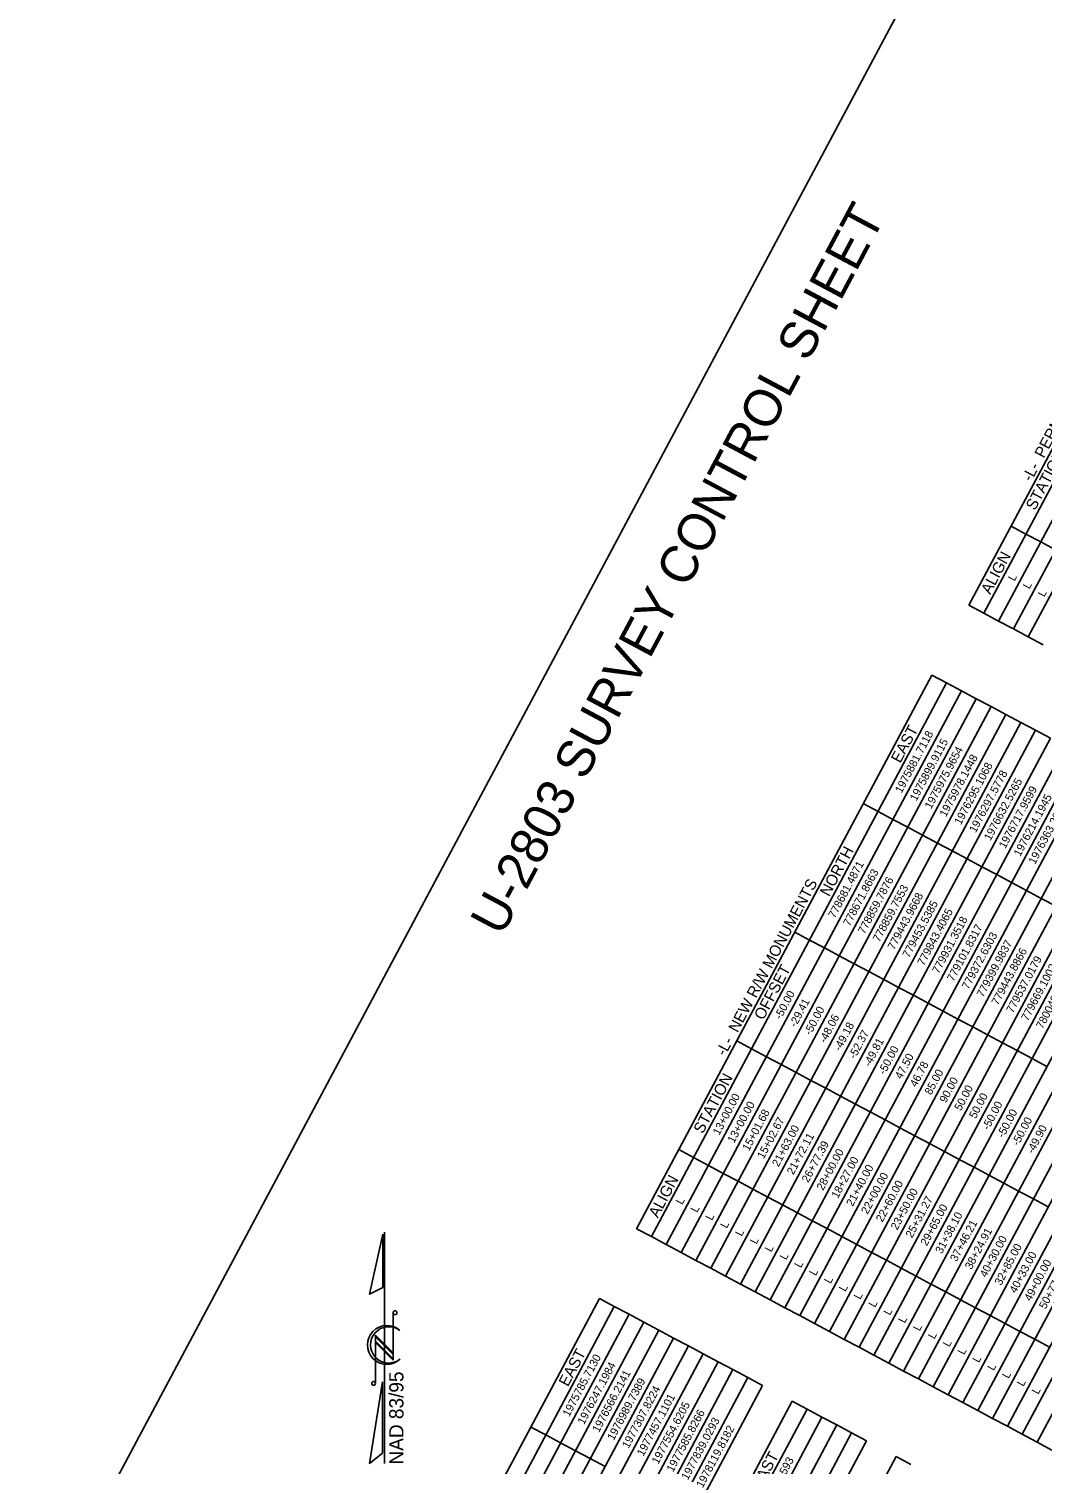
# Model space of a CAD drawing. Extents: x 1979034 to 1987549, y 771535 to 781988.
# Drawn here: x 1979034 to 1981883, y 775446 to 779481 of the extents above; entities that cross this region are included whole.
import ezdxf

# ---------------------------------------------------------------- set-up
doc = ezdxf.new("R2010")
doc.units = 0
for name, color, linetype in [('CTL Sheet Border CELL', 7, 'Continuous'), ('CTL Sheet Notes CELL', 7, 'Continuous'), ('CTL Sheet Table Cell', 7, 'Continuous'), ('CTL Sheet Text', 7, 'Continuous'), ('Old_Level_1', 7, 'Continuous'), ('Old_Level_11', 7, 'Continuous'), ('Sheet Data Field CELL', 7, 'Continuous')]:
    doc.layers.add(name, color=color, linetype=linetype)

msp = doc.modelspace()

# ---------------------------------------------------------------- linework, layer by layer
at = {"layer": 'CTL Sheet Border CELL'}
msp.add_lwpolyline([(1982714.7, 781848.1), (1979034.2, 774941.4), (1983868.8, 772365.1), (1987549.3, 779271.7)], close=True, dxfattribs=at)
at = {"layer": 'CTL Sheet Table Cell'}
for p, q in [((1981677, 777860.7), (1982506.6, 779417.5)), ((1981718.7, 777838.5), (1982548.3, 779395.2)), ((1981760.4, 777816.3), (1982590, 779373)), ((1981802.1, 777794), (1982631.7, 779350.8)), ((1981843.8, 777771.8), (1982673.4, 779328.6)), ((1981795.5, 778083.1), (1981837.2, 778060.9)), ((1981837.2, 778060.9), (1981878.9, 778038.7)), ((1981878.9, 778038.7), (1981920.6, 778016.4)), ((1981677, 777860.7), (1981718.7, 777838.5)), ((1981718.7, 777838.5), (1981760.4, 777816.3)), ((1981760.4, 777816.3), (1981802.1, 777794)), ((1981802.1, 777794), (1981843.8, 777771.8)), ((1981843.8, 777771.8), (1981885.5, 777749.6)), ((1980742.9, 776107.8), (1981572.5, 777664.5)), ((1981572.5, 777664.5), (1981614.2, 777642.3)), ((1980784.6, 776085.6), (1981614.2, 777642.3)), ((1980826.3, 776063.3), (1981655.9, 777620.1)), ((1981614.2, 777642.3), (1981655.9, 777620.1)), ((1981655.9, 777620.1), (1981697.6, 777597.9)), ((1980868, 776041.1), (1981697.6, 777597.9)), ((1980909.7, 776018.9), (1981739.3, 777575.7)), ((1981697.6, 777597.9), (1981739.3, 777575.7)), ((1981739.3, 777575.7), (1981781, 777553.4)), ((1980951.4, 775996.7), (1981781, 777553.4)), ((1980993.1, 775974.5), (1981822.7, 777531.2)), ((1981781, 777553.4), (1981822.7, 777531.2)), ((1981822.7, 777531.2), (1981864.4, 777509)), ((1981034.8, 775952.2), (1981864.4, 777509)), ((1981076.5, 775930), (1981906.1, 777486.8)), ((1981864.4, 777509), (1981906.1, 777486.8)), ((1981118.2, 775907.8), (1981947.8, 777464.6)), ((1981159.9, 775885.6), (1981989.5, 777442.3)), ((1981201.6, 775863.4), (1982031.2, 777420.1)), ((1981243.3, 775841.1), (1982072.9, 777397.9)), ((1981285, 775818.9), (1982114.6, 777375.7)), ((1981326.7, 775796.7), (1982156.3, 777353.5)), ((1981368.4, 775774.5), (1982198, 777331.2)), ((1981379.9, 777303.2), (1981421.6, 777280.9)), ((1981410.1, 775752.3), (1982239.7, 777309)), ((1981421.6, 777280.9), (1981463.3, 777258.7)), ((1981451.8, 775730), (1982281.4, 777286.8)), ((1981463.3, 777258.7), (1981505, 777236.5)), ((1981493.5, 775707.8), (1982323.1, 777264.6)), ((1981535.2, 775685.6), (1982364.8, 777242.3)), ((1981505, 777236.5), (1981546.7, 777214.3)), ((1981546.7, 777214.3), (1981588.4, 777192.1)), ((1981576.9, 775663.4), (1982406.5, 777220.1)), ((1981588.4, 777192.1), (1981630.1, 777169.8)), ((1981618.6, 775641.1), (1982448.2, 777197.9)), ((1981630.1, 777169.8), (1981671.8, 777147.6)), ((1981660.3, 775618.9), (1982489.9, 777175.7)), ((1981671.8, 777147.6), (1981713.5, 777125.4)), ((1981702, 775596.7), (1982531.6, 777153.5)), ((1981713.5, 777125.4), (1981755.2, 777103.2)), ((1981743.7, 775574.5), (1982573.3, 777131.2)), ((1981755.2, 777103.2), (1981796.9, 777080.9)), ((1981785.4, 775552.3), (1982615, 777109)), ((1981796.9, 777080.9), (1981838.6, 777058.7)), ((1981827.1, 775530), (1982656.7, 777086.8)), ((1981838.6, 777058.7), (1981880.3, 777036.5)), ((1981868.8, 775507.8), (1982698.4, 777064.6)), ((1981880.3, 777036.5), (1981922, 777014.3)), ((1981187.3, 776941.8), (1981229, 776919.5)), ((1981229, 776919.5), (1981270.7, 776897.3)), ((1981270.7, 776897.3), (1981312.4, 776875.1)), ((1981312.4, 776875.1), (1981354.1, 776852.9)), ((1981354.1, 776852.9), (1981395.8, 776830.7)), ((1981395.8, 776830.7), (1981437.5, 776808.4)), ((1981437.5, 776808.4), (1981479.2, 776786.2)), ((1981479.2, 776786.2), (1981520.9, 776764)), ((1981520.9, 776764), (1981562.6, 776741.8)), ((1981562.6, 776741.8), (1981604.3, 776719.6)), ((1981604.3, 776719.6), (1981646, 776697.3)), ((1981646, 776697.3), (1981687.7, 776675.1)), ((1981024.4, 776636), (1981066.1, 776613.8)), ((1981687.7, 776675.1), (1981729.4, 776652.9)), ((1981729.4, 776652.9), (1981771.1, 776630.7)), ((1981066.1, 776613.8), (1981107.8, 776591.5)), ((1981771.1, 776630.7), (1981812.8, 776608.5)), ((1981812.8, 776608.5), (1981854.5, 776586.2)), ((1981107.8, 776591.5), (1981149.5, 776569.3)), ((1981149.5, 776569.3), (1981191.2, 776547.1)), ((1981854.5, 776586.2), (1981896.2, 776564)), ((1981191.2, 776547.1), (1981232.9, 776524.9)), ((1981232.9, 776524.9), (1981274.6, 776502.6)), ((1981274.6, 776502.6), (1981316.3, 776480.4)), ((1981316.3, 776480.4), (1981358, 776458.2)), ((1981358, 776458.2), (1981399.7, 776436)), ((1981399.7, 776436), (1981441.4, 776413.8)), ((1981441.4, 776413.8), (1981483.1, 776391.5)), ((1981483.1, 776391.5), (1981524.8, 776369.3)), ((1981524.8, 776369.3), (1981566.5, 776347.1)), ((1980861.4, 776330.2), (1980903.1, 776308)), ((1981566.5, 776347.1), (1981608.2, 776324.9)), ((1981608.2, 776324.9), (1981649.9, 776302.7)), ((1980903.1, 776308), (1980944.8, 776285.7)), ((1980944.8, 776285.7), (1980986.5, 776263.5)), ((1981649.9, 776302.7), (1981691.6, 776280.4)), ((1981691.6, 776280.4), (1981733.3, 776258.2)), ((1980986.5, 776263.5), (1981028.2, 776241.3)), ((1981028.2, 776241.3), (1981069.9, 776219.1)), ((1981733.3, 776258.2), (1981775, 776236)), ((1981775, 776236), (1981816.7, 776213.8)), ((1981069.9, 776219.1), (1981111.6, 776196.9)), ((1981111.6, 776196.9), (1981153.3, 776174.6)), ((1981816.7, 776213.8), (1981858.4, 776191.6)), ((1981858.4, 776191.6), (1981900.1, 776169.3)), ((1981153.3, 776174.6), (1981195, 776152.4)), ((1981195, 776152.4), (1981236.7, 776130.2)), ((1981236.7, 776130.2), (1981278.4, 776108)), ((1980742.9, 776107.8), (1980784.6, 776085.6)), ((1980784.6, 776085.6), (1980826.3, 776063.3)), ((1981278.4, 776108), (1981320.1, 776085.8)), ((1981320.1, 776085.8), (1981361.8, 776063.5)), ((1980826.3, 776063.3), (1980868, 776041.1)), ((1980868, 776041.1), (1980909.7, 776018.9)), ((1981361.8, 776063.5), (1981403.5, 776041.3)), ((1981403.5, 776041.3), (1981445.2, 776019.1)), ((1980909.7, 776018.9), (1980951.4, 775996.7)), ((1980951.4, 775996.7), (1980993.1, 775974.5)), ((1981445.2, 776019.1), (1981486.9, 775996.9)), ((1981486.9, 775996.9), (1981528.6, 775974.6)), ((1980993.1, 775974.5), (1981034.8, 775952.2)), ((1981034.8, 775952.2), (1981076.5, 775930)), ((1981528.6, 775974.6), (1981570.3, 775952.4)), ((1981570.3, 775952.4), (1981612, 775930.2)), ((1980016.2, 774744.1), (1980638.4, 775911.6)), ((1980638.4, 775911.6), (1980680.1, 775889.4)), ((1981076.5, 775930), (1981118.2, 775907.8)), ((1981612, 775930.2), (1981653.7, 775908)), ((1980057.9, 774721.8), (1980680.1, 775889.4)), ((1980680.1, 775889.4), (1980721.8, 775867.2)), ((1981118.2, 775907.8), (1981159.9, 775885.6)), ((1981159.9, 775885.6), (1981201.6, 775863.4)), ((1981653.7, 775908), (1981695.4, 775885.8)), ((1981695.4, 775885.8), (1981737.1, 775863.5)), ((1980099.6, 774699.6), (1980721.8, 775867.2)), ((1980141.3, 774677.4), (1980763.5, 775845)), ((1980721.8, 775867.2), (1980763.5, 775845)), ((1980763.5, 775845), (1980805.2, 775822.8)), ((1981201.6, 775863.4), (1981243.3, 775841.1)), ((1981243.3, 775841.1), (1981285, 775818.9)), ((1981737.1, 775863.5), (1981778.8, 775841.3)), ((1981778.8, 775841.3), (1981820.5, 775819.1)), ((1980183, 774655.2), (1980805.2, 775822.8)), ((1980224.7, 774633), (1980846.9, 775800.5)), ((1980805.2, 775822.8), (1980846.9, 775800.5)), ((1980846.9, 775800.5), (1980888.6, 775778.3)), ((1981285, 775818.9), (1981326.7, 775796.7)), ((1981326.7, 775796.7), (1981368.4, 775774.5)), ((1981820.5, 775819.1), (1981862.2, 775796.9)), ((1981862.2, 775796.9), (1981903.9, 775774.7)), ((1980266.4, 774610.7), (1980888.6, 775778.3)), ((1980308.1, 774588.5), (1980930.3, 775756.1)), ((1980888.6, 775778.3), (1980930.3, 775756.1)), ((1980930.3, 775756.1), (1980972, 775733.9)), ((1981368.4, 775774.5), (1981410.1, 775752.3)), ((1981410.1, 775752.3), (1981451.8, 775730)), ((1980349.8, 774566.3), (1980972, 775733.9)), ((1980391.5, 774544.1), (1981013.7, 775711.6)), ((1980972, 775733.9), (1981013.7, 775711.6)), ((1981013.7, 775711.6), (1981055.4, 775689.4)), ((1981451.8, 775730), (1981493.5, 775707.8)), ((1981493.5, 775707.8), (1981535.2, 775685.6)), ((1980433.2, 774521.9), (1981055.4, 775689.4)), ((1980474.9, 774499.6), (1981097.1, 775667.2)), ((1981055.4, 775689.4), (1981097.1, 775667.2)), ((1981535.2, 775685.6), (1981576.9, 775663.4)), ((1981576.9, 775663.4), (1981618.6, 775641.1)), ((1981618.6, 775641.1), (1981660.3, 775618.9)), ((1980558.3, 774455.2), (1981180.5, 775622.8)), ((1980600, 774433), (1981222.2, 775600.5)), ((1981180.5, 775622.8), (1981222.2, 775600.5)), ((1981222.2, 775600.5), (1981263.9, 775578.3)), ((1981660.3, 775618.9), (1981702, 775596.7)), ((1981702, 775596.7), (1981743.7, 775574.5)), ((1980445.8, 775550.2), (1980487.5, 775528)), ((1980641.7, 774410.8), (1981263.9, 775578.3)), ((1980683.4, 774388.5), (1981305.6, 775556.1)), ((1981263.9, 775578.3), (1981305.6, 775556.1)), ((1981305.6, 775556.1), (1981347.3, 775533.9)), ((1981743.7, 775574.5), (1981785.4, 775552.3)), ((1981785.4, 775552.3), (1981827.1, 775530)), ((1980487.5, 775528), (1980529.2, 775505.8)), ((1980529.2, 775505.8), (1980570.9, 775483.6)), ((1980725.1, 774366.3), (1981347.3, 775533.9)), ((1980766.8, 774344.1), (1981389, 775511.7)), ((1981347.3, 775533.9), (1981389, 775511.7)), ((1981827.1, 775530), (1981868.8, 775507.8)), ((1981868.8, 775507.8), (1981910.5, 775485.6)), ((1980570.9, 775483.6), (1980612.6, 775461.4)), ((1980850.2, 774299.6), (1981472.4, 775467.2)), ((1981472.4, 775467.2), (1981514.1, 775445)), ((1980612.6, 775461.4), (1980654.3, 775439.1))]:
    msp.add_line(p, q, dxfattribs=at)
at = {"layer": 'Old_Level_1'}
for p, q in [((1980034, 775448), (1980034, 776098)), ((1980058.5, 775871.8), (1980058.5, 775738.4)), ((1980058.5, 775759.2), (1980008.8, 775808.9)), ((1980008.8, 775808.9), (1980008.8, 775673.3)), ((1980058.5, 775754.3), (1980008.8, 775804)), ((1980008.8, 775804), (1980008.8, 775791.8)), ((1980058.5, 775742.1), (1980008.8, 775791.8)), ((1980008.8, 775791.8), (1980058.5, 775742.1)), ((1980058.5, 775738.4), (1980008.8, 775788.1)), ((1980076.9, 775822.1), (1980077.6, 775821.6)), ((1980058.5, 775742.1), (1980058.5, 775754.3))]:
    msp.add_line(p, q, dxfattribs=at)
for points in [[(1980029.5, 776092.3), (1979992.4, 775923.5), (1980029.5, 775942.3)], [(1980028.7, 775677), (1979991.9, 775448), (1980028.7, 775477)]]:
    msp.add_lwpolyline(points, close=True, dxfattribs=at)
for centre in [(1980063.8, 775871.7), (1980003.5, 775673.1)]:
    msp.add_circle(centre, 5.3, dxfattribs=at)
for centre, radius, start, end in [((1980040.9, 775781.1), 54.6, 47.84, 312.3941), ((1980046.2, 775781.2), 51.2, 53.095, 308.6287)]:
    msp.add_arc(centre, radius, start, end, dxfattribs=at)

# ---------------------------------------------------------------- texts
at = {"layer": 'CTL Sheet Notes CELL'}
for s, p in [('-L-  PERMANENT UTILITY EASEMENTS', (1981852.2, 778206.1)), ('STATION', (1981862.8, 778125.5)), ('ALIGN', (1981736.7, 777889)), ('EAST', (1981484, 777414.8)), ('NORTH', (1981284.1, 777039.6)), ('-L-  NEW R/W MONUMENTS', (1980991.5, 776591.1)), ('OFFSET', (1981099, 776692.2)), ('STATION', (1980928.7, 776372.6)), ('ALIGN', (1980802.6, 776136.1)), ('EAST', (1980549.9, 775661.9)), ('EAST', (1981092, 775373))]:
    msp.add_text(s, height=31.5, rotation=61.9471, dxfattribs=at).set_placement(p)
at = {"layer": 'CTL Sheet Text'}
for s, p in [('L', (1981805.3, 777926.7)), ('L', (1981847, 777904.5)), ('L', (1981888.7, 777882.3)), ('1975881.7118', (1981487.4, 777330.3)), ('1975899.9115', (1981529.1, 777308.1)), ('1975975.9654', (1981570.8, 777285.9)), ('1975978.1448', (1981612.5, 777263.6)), ('1976295.1068', (1981654.2, 777241.4)), ('1976297.5778', (1981695.9, 777219.2)), ('1976632.5265', (1981737.6, 777197)), ('1976717.9599', (1981779.3, 777174.8)), ('1976214.1945', (1981821, 777152.5)), ('1976363.2885', (1981862.7, 777130.3)), ('778681.4871', (1981300.1, 776978.8)), ('778671.8663', (1981341.8, 776956.5)), ('778859.7876', (1981383.5, 776934.3)), ('778859.7553', (1981425.2, 776912.1)), ('779443.9668', (1981466.9, 776889.9)), ('779453.5385', (1981508.6, 776867.7)), ('779843.4065', (1981550.3, 776845.4)), ('779931.3518', (1981592, 776823.2)), ('779101.8317', (1981633.7, 776801)), ('779372.6303', (1981675.4, 776778.8)), ('779399.9837', (1981717.1, 776756.6)), ('779443.8866', (1981758.8, 776734.3)), ('779537.0179', (1981800.5, 776712.1)), ('779669.1002', (1981842.2, 776689.9)), ('780049.5205', (1981883.9, 776667.7)), ('-50.00', (1981148.6, 776694.4)), ('-29.41', (1981190.3, 776672.2)), ('-50.00', (1981232, 776650)), ('-48.06', (1981273.7, 776627.8)), ('-49.18', (1981315.4, 776605.5)), ('-52.37', (1981357.1, 776583.3)), ('-49.81', (1981398.8, 776561.1)), ('-50.00', (1981440.5, 776538.9)), ('47.50', (1981487.4, 776526.5)), ('46.78', (1981529.1, 776504.3)), ('85.00', (1981570.8, 776482.1)), ('90.00', (1981612.5, 776459.8)), ('13+00.00', (1980975.1, 776368.9)), ('50.00', (1981654.2, 776437.6)), ('50.00', (1981695.9, 776415.4)), ('13+00.00', (1981016.8, 776346.7)), ('15+01.68', (1981058.5, 776324.5)), ('-50.00', (1981732.4, 776383.3)), ('-50.00', (1981774.1, 776361.1)), ('15+02.67', (1981100.2, 776302.3)), ('21+63.00', (1981141.9, 776280.1)), ('-50.00', (1981815.8, 776338.9)), ('-49.90', (1981857.5, 776316.7)), ('21+72.11', (1981183.6, 776257.8)), ('26+77.39', (1981225.3, 776235.6)), ('28+00.00', (1981267, 776213.4)), ('18+27.00', (1981308.7, 776191.2)), ('21+40.00', (1981350.4, 776169)), ('22+00.00', (1981392.1, 776146.7)), ('22+60.00', (1981433.8, 776124.5)), ('23+50.00', (1981475.5, 776102.3)), ('25+31.27', (1981517.2, 776080.1)), ('L', (1980871.1, 776173.8)), ('L', (1980912.8, 776151.6)), ('29+65.00', (1981558.9, 776057.8)), ('31+38.10', (1981600.6, 776035.6)), ('L', (1980954.5, 776129.4)), ('L', (1980996.2, 776107.1)), ('37+46.21', (1981642.3, 776013.4)), ('L', (1981037.9, 776084.9)), ('L', (1981079.6, 776062.7)), ('38+24.91', (1981684, 775991.2)), ('40+30.00', (1981725.7, 775969)), ('L', (1981121.3, 776040.5)), ('L', (1981163, 776018.3)), ('32+85.00', (1981767.4, 775946.7)), ('40+33.00', (1981809.1, 775924.5)), ('L', (1981204.7, 775996)), ('49+00.00', (1981850.8, 775902.3)), ('50+77.24', (1981892.5, 775880.1)), ('L', (1981246.4, 775973.8)), ('L', (1981288.1, 775951.6)), ('L', (1981329.8, 775929.4)), ('L', (1981371.5, 775907.1)), ('L', (1981413.2, 775884.9)), ('L', (1981454.9, 775862.7)), ('L', (1981496.6, 775840.5)), ('L', (1981538.3, 775818.3)), ('L', (1981580, 775796)), ('L', (1981621.7, 775773.8)), ('1975785.7130', (1980553.3, 775577.4)), ('L', (1981663.4, 775751.6)), ('1976247.1984', (1980595, 775555.2)), ('1976566.2141', (1980636.7, 775533)), ('L', (1981705.1, 775729.4)), ('L', (1981746.8, 775707.2)), ('1976989.7389', (1980678.4, 775510.7)), ('L', (1981788.5, 775684.9)), ('L', (1981830.2, 775662.7)), ('1977307.8224', (1980720.1, 775488.5)), ('1977457.1101', (1980761.8, 775466.3)), ('L', (1981871.9, 775640.5)), ('1977554.6205', (1980803.5, 775444.1)), ('1977585.8266', (1980845.2, 775421.9)), ('1977839.0293', (1980886.9, 775399.6)), ('1978119.8182', (1980928.6, 775377.4)), ('1976522.1593', (1981095.4, 775288.5))]:
    msp.add_text(s, height=22.5, rotation=61.9471, dxfattribs=at).set_placement(p)
at = {"layer": 'Old_Level_11'}
msp.add_text('NAD 83/95', height=40, rotation=90, dxfattribs=at).set_placement((1980087.5, 775444.8))
at = {"layer": 'Sheet Data Field CELL'}
msp.add_text('U-2803 SURVEY CONTROL SHEET', height=104.348, rotation=61.9471, dxfattribs=at).set_placement((1980363.6, 776926.8))

doc.saveas('drawing.dxf')
